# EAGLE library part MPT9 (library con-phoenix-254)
PHOENIX CONNECTOR
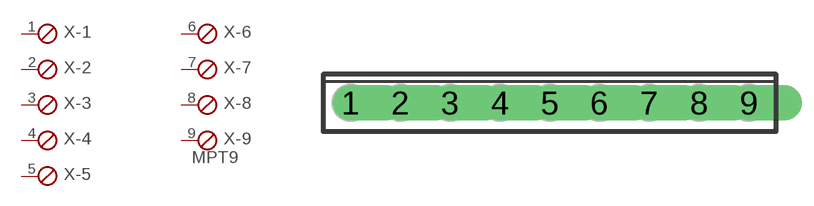
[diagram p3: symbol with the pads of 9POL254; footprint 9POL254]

Designator prefix X; gates -1=SKB -2=SKB -3=SKB -4=SKB -5=SKB -6=SKB -7=SKB -8=SKB -9=SKBV

## MPT9  [9POL254]
1  -1:1  pas
2  -2:1  pas
3  -3:1  pas
4  -4:1  pas
5  -5:1  pas
6  -6:1  pas
7  -7:1  pas
8  -8:1  pas
9  -9:1  pas

## Footprint 9POL254 (pad centres in mm)
PHOENIX CONNECTOR
drill 1.2 offset: 1 -10.16,0; 2 -7.62,0; 3 -5.08,0; 4 -2.54,0; 5 0,0; 6 2.54,0; 7 5.08,0; 8 7.62,0; 9 10.16,0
